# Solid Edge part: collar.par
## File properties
Title: Collar
Author: Abhinav Rai
Template: Normal.par
Last saved by: CADCIM
Revision: 7
Application: Solid Edge
Density: 0.0000078 kg/mm^3
Accuracy: 0.01
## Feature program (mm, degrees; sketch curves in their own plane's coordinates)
sketch for "unnamed RevolvedProtrusion 1" plane through (0, 0, 0) normal (0, -1, 0) x-axis (1, 0, 0)
  line (6.5405, -15.9527) -> (9.1186, -15.9527)
  line (9.1186, -15.9527) -> (9.1186, -36.5775)
  line (9.1186, -36.5775) -> (6.5405, -36.5775)
  line (6.5405, -15.9527) -> (6.5405, -36.5775)
revolve "unnamed RevolvedProtrusion 1" add finite 360 deg
sketch for "unnamed Cutout 1" plane through (0, 0, 0) normal (0, -1, 0) x-axis (1, 0, 0)
  line (-1.1811, -15.9527) -> (1.1811, -15.9527)
  line (1.1811, -15.9527) -> (1.1811, -19.1277)
  line (1.1811, -19.1277) -> (-1.1811, -19.1277)
  line (-1.1811, -19.1277) -> (-1.1811, -15.9527)
extrude "unnamed Cutout 1" cut finite 50.8 symmetric
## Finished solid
Body 1: solid body, 11 faces, 26 edges, 16 vertices.
  Faces by surface: plane 9, cylinder 2
  Edges by curve: line 16, circle 10
Bounding box of the edges (mm): 18.237 x 18.237 x 20.625, from (-9.1186, -9.1186, -36.5775) to (9.1186, 9.1186, -15.9527).
Cylindrical faces by radius (mm): R6.5405 x1, R9.1186 x1
Planar faces by outward normal: +x 2, +z 4, -x 2, -z 1
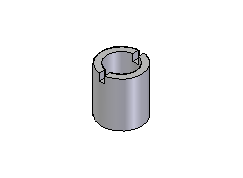
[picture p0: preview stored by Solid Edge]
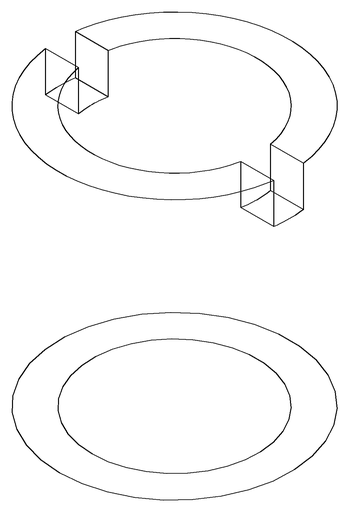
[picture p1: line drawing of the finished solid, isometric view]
